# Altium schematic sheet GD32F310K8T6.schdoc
size 127 x 101 mm
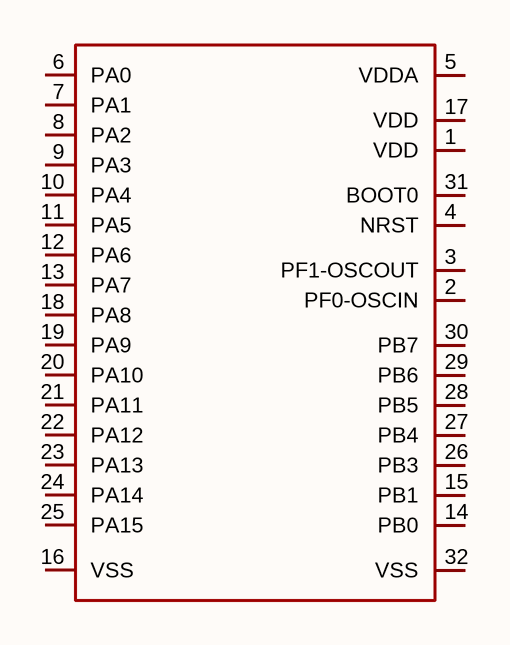
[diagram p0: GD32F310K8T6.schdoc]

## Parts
U?  gd32f310k8t6  [LQFP-32_L7.0-W7.0-P0.80-LS9.0-BL]  (value not drawn)

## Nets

Not connected (* = marked no-connect by the designer): U? 1(VDD) 2(PF0-OSCIN) 3(PF1-OSCOUT) 4(NRST) 5(VDDA) 6(PA0) 7(PA1) 8(PA2) 9(PA3) 10(PA4) 11(PA5) 12(PA6) 13(PA7) 14(PB0) 15(PB1) 16(VSS) 17(VDD) 18(PA8) 19(PA9) 20(PA10) 21(PA11) 22(PA12) 23(PA13) 24(PA14) 25(PA15) 26(PB3) 27(PB4) 28(PB5) 29(PB6) 30(PB7) 31(BOOT0) 32(VSS)

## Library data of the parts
U? = gd32f310k8t6: CPU内核:ARM Cortex-M4;CPU最大主频:72MHz;; Manufacturer: GigaDevice(兆易创新); AddInBom: yes; ModelId: 9b055eb510f041fea358114a6302af34; ModelName: LQFP-32_L7.0-W7.0-H1.4-LS9.0-P0.80; ModelTransform: 354.331,354.331,0,0,0,0,0,0,0; CPU Maximum Speed: 72MHz; Program Storage Size: 64KB; Program Memory Type: FLASH; Number of I/O: 39; ADC (Bit): 12bit; Voltage - Supply: 2.6V~3.6V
